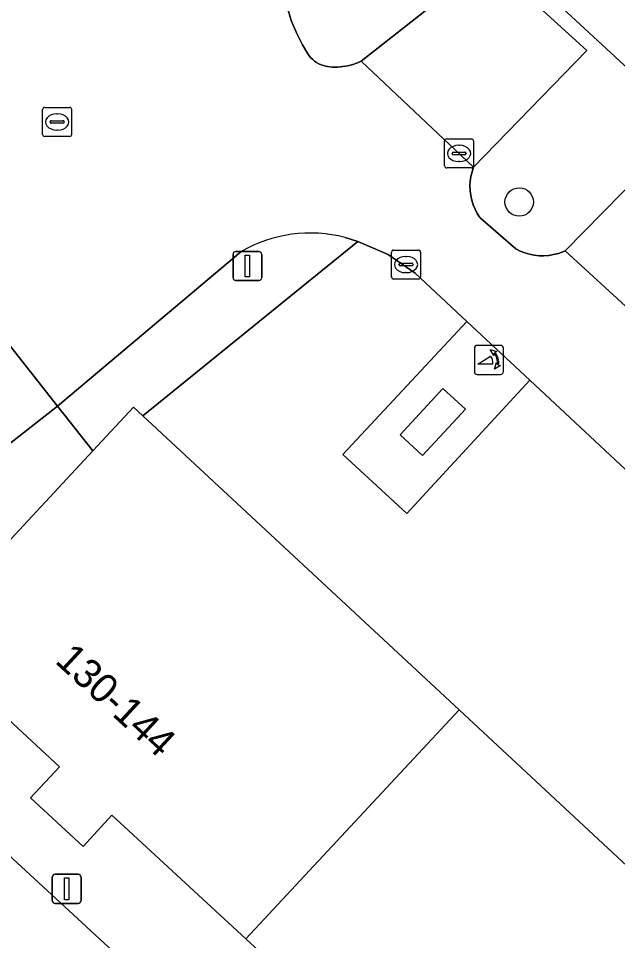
# Model space of a CAD drawing. Extents: x 159217 to 160349, y 381246 to 382172.
# Drawn here: x 159840.87 to 159861.49, y 381785.53 to 381817.29 of the extents above; entities that cross this region are included whole.
import ezdxf

# ---------------------------------------------------------------- set-up
doc = ezdxf.new("R2010")
doc.units = 0
for name, color, linetype in [('IMGEO_Boom', 7, 'Continuous'), ('IMGEO_Groenvoorziening', 7, 'Continuous'), ('IMGEO_Kolk', 7, 'Continuous'), ('IMGEO_Lichtmast', 7, 'Continuous'), ('IMGEO_Pand', 7, 'Continuous'), ('IMGEO_Pand_nummerreeks', 7, 'Continuous'), ('IMGEO_Parkeervlak_open', 7, 'Continuous'), ('IMGEO_Poller', 7, 'Continuous'), ('IMGEO_Rijbaan_lokaal_open', 7, 'Continuous'), ('IMGEO_Voetpad_open', 7, 'Continuous')]:
    doc.layers.add(name, color=color, linetype=linetype)

msp = doc.modelspace()

# ---------------------------------------------------------------- linework, layer by layer
at = {"layer": 'IMGEO_Boom'}
msp.add_circle((159858.108, 381810.97), 0.489, dxfattribs=at)
at = {"layer": 'IMGEO_Groenvoorziening'}
msp.add_lwpolyline([(159867.064, 381828.317), (159860.232, 381822.905), (159856.837, 381820.215), (159857.487, 381819.613), (159889.337, 381790.147)], dxfattribs=at)
for points in [[(159868.497, 381795.466), (159858.477, 381804.83), (159854.243, 381800.238), (159852.037, 381802.271), (159856.308, 381806.857), (159854.533, 381808.516), (159853.599, 381809.162), (159852.558, 381809.614), (159845.153, 381803.609), (159856.038, 381793.481), (159867.103, 381783.184), (159878.104, 381772.948), (159870.993, 381765.25), (159871.741, 381764.412), (159885.976, 381779.132), (159880.254, 381784.48), (159876.033, 381779.938), (159873.874, 381781.948), (159878.074, 381786.517), (159870.673, 381793.433), (159866.474, 381788.854), (159864.295, 381790.881)], [(159856.257, 381803.838), (159855.485, 381804.55), (159854.007, 381802.947), (159854.779, 381802.235)]]:
    msp.add_lwpolyline(points, close=True, dxfattribs=at)
at = {"layer": 'IMGEO_Kolk'}
for p, q in [((159841.704, 381813.299), (159841.704, 381814.151)), ((159841.779, 381814.225), (159842.631, 381814.225)), ((159842.192, 381814.005), (159842.217, 381814.005)), ((159842.705, 381814.151), (159842.705, 381813.299)), ((159841.963, 381813.719), (159841.963, 381813.731)), ((159842.401, 381813.682), (159842.003, 381813.682)), ((159842.006, 381813.768), (159842.404, 381813.768)), ((159842.447, 381813.731), (159842.447, 381813.719)), ((159842.215, 381813.445), (159842.19, 381813.445)), ((159842.631, 381813.225), (159841.779, 381813.225)), ((159855.537, 381812.215), (159855.537, 381813.067)), ((159855.612, 381813.141), (159856.464, 381813.141)), ((159856.538, 381813.067), (159856.538, 381812.215)), ((159856.025, 381812.921), (159856.05, 381812.921)), ((159855.796, 381812.635), (159855.796, 381812.647)), ((159856.234, 381812.598), (159855.836, 381812.598)), ((159855.839, 381812.684), (159856.237, 381812.684)), ((159856.28, 381812.647), (159856.28, 381812.635)), ((159856.464, 381812.141), (159855.612, 381812.141)), ((159856.048, 381812.361), (159856.023, 381812.361)), ((159853.712, 381808.389), (159853.712, 381809.241)), ((159853.787, 381809.315), (159854.639, 381809.315)), ((159854.713, 381809.241), (159854.713, 381808.389)), ((159854.2, 381809.095), (159854.225, 381809.095)), ((159853.971, 381808.809), (159853.971, 381808.821)), ((159854.409, 381808.772), (159854.011, 381808.772)), ((159854.014, 381808.858), (159854.412, 381808.858)), ((159854.455, 381808.821), (159854.455, 381808.809)), ((159854.639, 381808.315), (159853.787, 381808.315)), ((159854.223, 381808.535), (159854.198, 381808.535))]:
    msp.add_line(p, q, dxfattribs=at)
for points in [[(159841.704, 381813.299), (159841.704, 381814.151)], [(159841.779, 381814.225), (159842.631, 381814.225)], [(159842.705, 381814.151), (159842.705, 381813.299)], [(159842.631, 381813.225), (159841.779, 381813.225)], [(159855.537, 381812.215), (159855.537, 381813.067)], [(159855.612, 381813.141), (159856.464, 381813.141)], [(159856.538, 381813.067), (159856.538, 381812.215)], [(159856.464, 381812.141), (159855.612, 381812.141)], [(159853.712, 381808.389), (159853.712, 381809.241)], [(159853.787, 381809.315), (159854.639, 381809.315)], [(159854.713, 381809.241), (159854.713, 381808.389)], [(159854.639, 381808.315), (159853.787, 381808.315)]]:
    msp.add_lwpolyline(points, dxfattribs=at)
for centre, radius, start, end in [((159841.781, 381814.149), 0.0765, 91.552, 178.448), ((159841.781, 381814.149), 0.0765, 91.552, 178.448), ((159842.629, 381814.149), 0.0765, 1.552, 88.448), ((159842.629, 381814.149), 0.0765, 1.552, 88.448), ((159842.003, 381813.728), 0.0403, 85.8775, 175.7526), ((159842, 381813.718), 0.0366, 178.938, 274.7102), ((159842.404, 381813.725), 0.043, 264.8664, 352.4533), ((159842.408, 381813.73), 0.0386, 1.7309, 96.639), ((159841.781, 381813.301), 0.0765, 181.552, 268.448), ((159841.781, 381813.301), 0.0765, 181.552, 268.448), ((159842.629, 381813.301), 0.0765, 271.552, 358.448), ((159842.629, 381813.301), 0.0765, 271.552, 358.448), ((159855.614, 381813.065), 0.0765, 91.552, 178.448), ((159855.614, 381813.065), 0.0765, 91.552, 178.448), ((159856.462, 381813.065), 0.0765, 1.552, 88.448), ((159856.462, 381813.065), 0.0765, 1.552, 88.448), ((159855.836, 381812.644), 0.0403, 85.8775, 175.7526), ((159855.833, 381812.634), 0.0366, 178.938, 274.7102), ((159856.237, 381812.641), 0.043, 264.8664, 352.4533), ((159856.241, 381812.646), 0.0386, 1.7309, 96.639), ((159855.614, 381812.217), 0.0765, 181.552, 268.448), ((159855.614, 381812.217), 0.0765, 181.552, 268.448), ((159856.462, 381812.217), 0.0765, 271.552, 358.448), ((159856.462, 381812.217), 0.0765, 271.552, 358.448), ((159853.789, 381809.239), 0.0765, 91.552, 178.448), ((159853.789, 381809.239), 0.0765, 91.552, 178.448), ((159854.637, 381809.239), 0.0765, 1.552, 88.448), ((159854.637, 381809.239), 0.0765, 1.552, 88.448), ((159854.011, 381808.818), 0.0403, 85.8775, 175.7526), ((159854.008, 381808.808), 0.0366, 178.938, 274.7102), ((159854.412, 381808.815), 0.043, 264.8664, 352.4533), ((159854.416, 381808.82), 0.0386, 1.7309, 96.639), ((159853.789, 381808.391), 0.0765, 181.552, 268.448), ((159853.789, 381808.391), 0.0765, 181.552, 268.448), ((159854.637, 381808.391), 0.0765, 271.552, 358.448), ((159854.637, 381808.391), 0.0765, 271.552, 358.448)]:
    msp.add_arc(centre, radius, start, end, dxfattribs=at)
for centre, major_axis, ratio, start_param, end_param in [((159842.191, 381813.725), (-0.387, 0.002), 0.722429, 4.712389, 7.853982), ((159842.216, 381813.725), (-0.39, 0.002), 0.717154, 1.570796, 4.712389), ((159856.024, 381812.641), (-0.387, 0.002), 0.722429, 4.712389, 7.853982), ((159856.049, 381812.641), (-0.39, 0.002), 0.717154, 1.570796, 4.712389), ((159854.199, 381808.815), (-0.387, 0.002), 0.722429, 4.712389, 7.853982), ((159854.224, 381808.815), (-0.39, 0.002), 0.717154, 1.570796, 4.712389)]:
    msp.add_ellipse(centre, major_axis=major_axis, ratio=ratio, start_param=start_param, end_param=end_param, dxfattribs=at)
at = {"layer": 'IMGEO_Lichtmast'}
for p, q in [((159848.358, 381809.266), (159849.148, 381809.266)), ((159849.148, 381809.266), (159848.358, 381809.266)), ((159848.258, 381808.366), (159848.258, 381809.166)), ((159848.258, 381809.166), (159848.258, 381808.366)), ((159849.248, 381809.166), (159849.248, 381808.366)), ((159849.248, 381808.366), (159849.248, 381809.166)), ((159849.148, 381808.266), (159848.358, 381808.266)), ((159848.358, 381808.266), (159849.148, 381808.266)), ((159842.037, 381786.914), (159842.037, 381787.714)), ((159842.037, 381787.714), (159842.037, 381786.914)), ((159842.137, 381787.814), (159842.927, 381787.814)), ((159842.927, 381787.814), (159842.137, 381787.814)), ((159843.027, 381787.714), (159843.027, 381786.914)), ((159843.027, 381786.914), (159843.027, 381787.714)), ((159842.927, 381786.814), (159842.137, 381786.814)), ((159842.137, 381786.814), (159842.927, 381786.814))]:
    msp.add_line(p, q, dxfattribs=at)
for points in [[(159848.678, 381809.141), (159848.828, 381809.141), (159848.828, 381808.391), (159848.678, 381808.391), (159848.678, 381809.141)], [(159842.457, 381787.689), (159842.607, 381787.689), (159842.607, 381786.939), (159842.457, 381786.939), (159842.457, 381787.689)]]:
    msp.add_lwpolyline(points, dxfattribs=at)
for centre, start, end in [((159848.358, 381809.166), 90, 180), ((159848.358, 381809.166), 90, 180), ((159849.148, 381809.166), 0, 90), ((159849.148, 381809.166), 360, 90), ((159848.358, 381808.366), 180, 270), ((159848.358, 381808.366), 180, 270), ((159849.148, 381808.366), 270, 0), ((159849.148, 381808.366), 270, 0), ((159842.137, 381787.714), 90, 180), ((159842.137, 381787.714), 90, 180), ((159842.927, 381787.714), 0, 90), ((159842.927, 381787.714), 360, 90), ((159842.137, 381786.914), 180, 270), ((159842.137, 381786.914), 180, 270), ((159842.927, 381786.914), 270, 0), ((159842.927, 381786.914), 270, 0)]:
    msp.add_arc(centre, 0.1, start, end, dxfattribs=at)
at = {"layer": 'IMGEO_Pand'}
for points in [[(159840.364, 381806.301), (159835.454, 381802.453), (159837.309, 381800.087), (159842.218, 381803.935)], [(159848.695, 381785.59), (159856.038, 381793.481), (159845.153, 381803.609), (159844.839, 381803.901), (159843.436, 381802.394), (159837.463, 381795.978), (159842.281, 381791.521), (159841.291, 381790.448), (159843.097, 381788.778), (159844.089, 381789.85)], [(159848.695, 381785.59), (159853.302, 381781.33), (159852.311, 381780.259), (159854.139, 381778.568), (159855.131, 381779.641), (159859.793, 381775.329), (159867.103, 381783.184), (159856.038, 381793.481)]]:
    msp.add_lwpolyline(points, close=True, dxfattribs=at)
at = {"layer": 'IMGEO_Parkeervlak_open'}
for points in [[(159852.671, 381815.822), (159856.536, 381812.167), (159860.441, 381816.186), (159857.051, 381819.27)], [(159859.685, 381809.285), (159884.961, 381786.098), (159885.291, 381786.48), (159888.672, 381790.031), (159863.597, 381813.276)]]:
    msp.add_lwpolyline(points, close=True, dxfattribs=at)
at = {"layer": 'IMGEO_Poller'}
for p, q in [((159857.468, 381806.029), (159856.66, 381806.029)), ((159857.468, 381806.029), (159856.66, 381806.029)), ((159856.566, 381805.934), (159856.566, 381805.127)), ((159856.566, 381805.934), (159856.566, 381805.127)), ((159857.562, 381805.127), (159857.562, 381805.934)), ((159857.562, 381805.127), (159857.562, 381805.934)), ((159856.66, 381805.032), (159857.468, 381805.032)), ((159856.66, 381805.032), (159857.468, 381805.032))]:
    msp.add_line(p, q, dxfattribs=at)
for points in [[(159857.245, 381805.758), (159857.233, 381805.685), (159857.108, 381805.89)], [(159857.108, 381805.89), (159857.339, 381805.824), (159857.268, 381805.792)], [(159857.201, 381805.385), (159856.688, 381805.385), (159857.118, 381805.66)], [(159857.261, 381805.213), (159857.327, 381805.444), (159857.357, 381805.376)], [(159857.393, 381805.349), (159857.465, 381805.338), (159857.261, 381805.213)]]:
    msp.add_lwpolyline(points, dxfattribs=at)
for centre, radius, start, end in [((159856.66, 381805.934), 0.0946, 90, 180), ((159856.66, 381805.934), 0.0946, 90, 180), ((159857.468, 381805.934), 0.0946, 0, 90), ((159857.468, 381805.934), 0.0946, 0, 90), ((159856.887, 381805.445), 0.476, 351.7527, 41.1691), ((159856.887, 381805.445), 0.516, 349.3569, 42.2912), ((159856.873, 381805.435), 0.332, 351.3247, 42.4854), ((159856.66, 381805.127), 0.0946, 180, 270), ((159856.66, 381805.127), 0.0946, 180, 270), ((159857.468, 381805.127), 0.0946, 270, 0), ((159857.468, 381805.127), 0.0946, 270, 0)]:
    msp.add_arc(centre, radius, start, end, dxfattribs=at)
at = {"layer": 'IMGEO_Rijbaan_lokaal_open'}
for points in [[(159836.112, 381817.679), (159832.946, 381815.765), (159834.8, 381813.399), (159836.522, 381811.203), (159838.42, 381808.78), (159840.364, 381806.301), (159842.218, 381803.935), (159848.527, 381809.25)], [(159884.961, 381786.098), (159859.685, 381809.285), (159859.613, 381809.254), (159859.455, 381809.198), (159859.292, 381809.156), (159859.126, 381809.129), (159858.959, 381809.116), (159858.79, 381809.119), (159858.623, 381809.137), (159858.458, 381809.169), (159858.297, 381809.216), (159858.14, 381809.278), (159857.99, 381809.353), (159856.777, 381810.409), (159856.755, 381810.44), (159856.665, 381810.578), (159856.589, 381810.724), (159856.525, 381810.876), (159856.476, 381811.033), (159856.441, 381811.194), (159856.42, 381811.358), (159856.414, 381811.523), (159856.423, 381811.687), (159856.446, 381811.85), (159856.484, 381812.011), (159856.536, 381812.167), (159852.671, 381815.822), (159852.542, 381815.763), (159852.377, 381815.704), (159852.208, 381815.659), (159852.035, 381815.63), (159851.86, 381815.616), (159851.685, 381815.618), (159851.51, 381815.636), (159851.453, 381815.646), (159851.37, 381815.667), (159851.289, 381815.695), (159851.211, 381815.73), (159851.137, 381815.772), (159851.066, 381815.821), (159851.001, 381815.876), (159850.94, 381815.936), (159850.885, 381816.002), (159850.836, 381816.072), (159850.647, 381816.379), (159850.438, 381816.79), (159850.265, 381817.218), (159850.132, 381817.66)], [(159852.118, 381809.746), (159852.558, 381809.614), (159853.599, 381809.162), (159854.533, 381808.516), (159856.308, 381806.857), (159858.477, 381804.83), (159868.497, 381795.466)], [(159869.262, 381761.943), (159836.624, 381792.091), (159834.612, 381793.898), (159834.039, 381794.273), (159833.435, 381794.596), (159832.804, 381794.863), (159832.152, 381795.073), (159831.484, 381795.224), (159830.805, 381795.314), (159830.121, 381795.344), (159829.437, 381795.312), (159828.758, 381795.219), (159828.09, 381795.066), (159827.439, 381794.854), (159826.809, 381794.585), (159826.206, 381794.26), (159825.925, 381794.084), (159791.101, 381766.789)]]:
    msp.add_lwpolyline(points, dxfattribs=at)
msp.add_arc((159850.92, 381805.175), 4.726, 75.3113, 120.4169, dxfattribs=at)
at = {"layer": 'IMGEO_Voetpad_open'}
for points in [[(159889.337, 381790.147), (159857.487, 381819.613)], [(159850.132, 381817.66), (159850.265, 381817.218), (159850.438, 381816.79), (159850.647, 381816.379), (159850.836, 381816.072), (159850.885, 381816.002), (159850.94, 381815.936), (159851.001, 381815.876), (159851.066, 381815.821), (159851.137, 381815.772), (159851.211, 381815.73), (159851.289, 381815.695), (159851.37, 381815.667), (159851.453, 381815.646), (159851.51, 381815.636), (159851.685, 381815.618), (159851.86, 381815.616), (159852.035, 381815.63), (159852.208, 381815.659), (159852.377, 381815.704), (159852.542, 381815.763), (159852.671, 381815.822), (159857.051, 381819.27)], [(159857.051, 381819.27), (159860.441, 381816.186), (159856.536, 381812.167), (159856.484, 381812.011), (159856.446, 381811.85), (159856.423, 381811.687), (159856.414, 381811.523), (159856.42, 381811.358), (159856.441, 381811.194), (159856.476, 381811.033), (159856.525, 381810.876), (159856.589, 381810.724), (159856.665, 381810.578), (159856.755, 381810.44), (159856.777, 381810.409), (159857.99, 381809.353), (159858.14, 381809.278), (159858.297, 381809.216), (159858.458, 381809.169), (159858.623, 381809.137), (159858.79, 381809.119), (159858.959, 381809.116), (159859.126, 381809.129), (159859.292, 381809.156), (159859.455, 381809.198), (159859.613, 381809.254), (159859.685, 381809.285), (159863.597, 381813.276)], [(159848.527, 381809.25), (159842.218, 381803.935), (159843.436, 381802.394), (159844.839, 381803.901), (159845.153, 381803.609), (159852.558, 381809.614), (159852.118, 381809.746)], [(159853.302, 381781.33), (159848.695, 381785.59), (159844.089, 381789.85), (159843.097, 381788.778), (159841.291, 381790.448), (159842.281, 381791.521), (159837.463, 381795.978), (159843.436, 381802.394), (159842.218, 381803.935), (159837.309, 381800.087), (159835.454, 381802.453), (159833.708, 381804.681), (159828.641, 381800.71), (159829.534, 381799.569), (159827.597, 381798.052), (159826.705, 381799.192), (159821.766, 381795.321), (159816.827, 381791.45), (159817.718, 381790.312), (159815.781, 381788.795), (159814.891, 381789.932), (159809.975, 381786.08)], [(159791.101, 381766.789), (159825.925, 381794.084), (159826.206, 381794.26), (159826.809, 381794.585), (159827.439, 381794.854), (159828.09, 381795.066), (159828.758, 381795.219), (159829.437, 381795.312), (159830.121, 381795.344), (159830.805, 381795.314), (159831.484, 381795.224), (159832.152, 381795.073), (159832.804, 381794.863), (159833.435, 381794.596), (159834.039, 381794.273), (159834.612, 381793.898), (159836.624, 381792.091), (159869.262, 381761.943)]]:
    msp.add_lwpolyline(points, dxfattribs=at)
for points in [[(159856.308, 381806.857), (159852.037, 381802.271), (159854.243, 381800.238), (159858.477, 381804.83)], [(159854.779, 381802.235), (159854.007, 381802.947), (159855.485, 381804.55), (159856.257, 381803.838)]]:
    msp.add_lwpolyline(points, close=True, dxfattribs=at)
msp.add_arc((159850.92, 381805.175), 4.726, 75.3113, 120.4169, dxfattribs=at)

# ---------------------------------------------------------------- texts
at = {"layer": 'IMGEO_Pand_nummerreeks'}
msp.add_text('130-144', height=1, rotation=317.2368, dxfattribs=at).set_placement((159842.098, 381795.124))

doc.saveas('drawing.dxf')
